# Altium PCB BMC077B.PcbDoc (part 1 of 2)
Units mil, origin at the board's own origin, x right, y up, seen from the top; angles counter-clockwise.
Board outline 3180 x 2450 mil, 4 copper layers (Top Layer, Signal Layer 1, Signal Layer 2, Bottom Layer), stack 61.2 mil thick; 102 components, 30 nets, 186 pads, 124 vias.
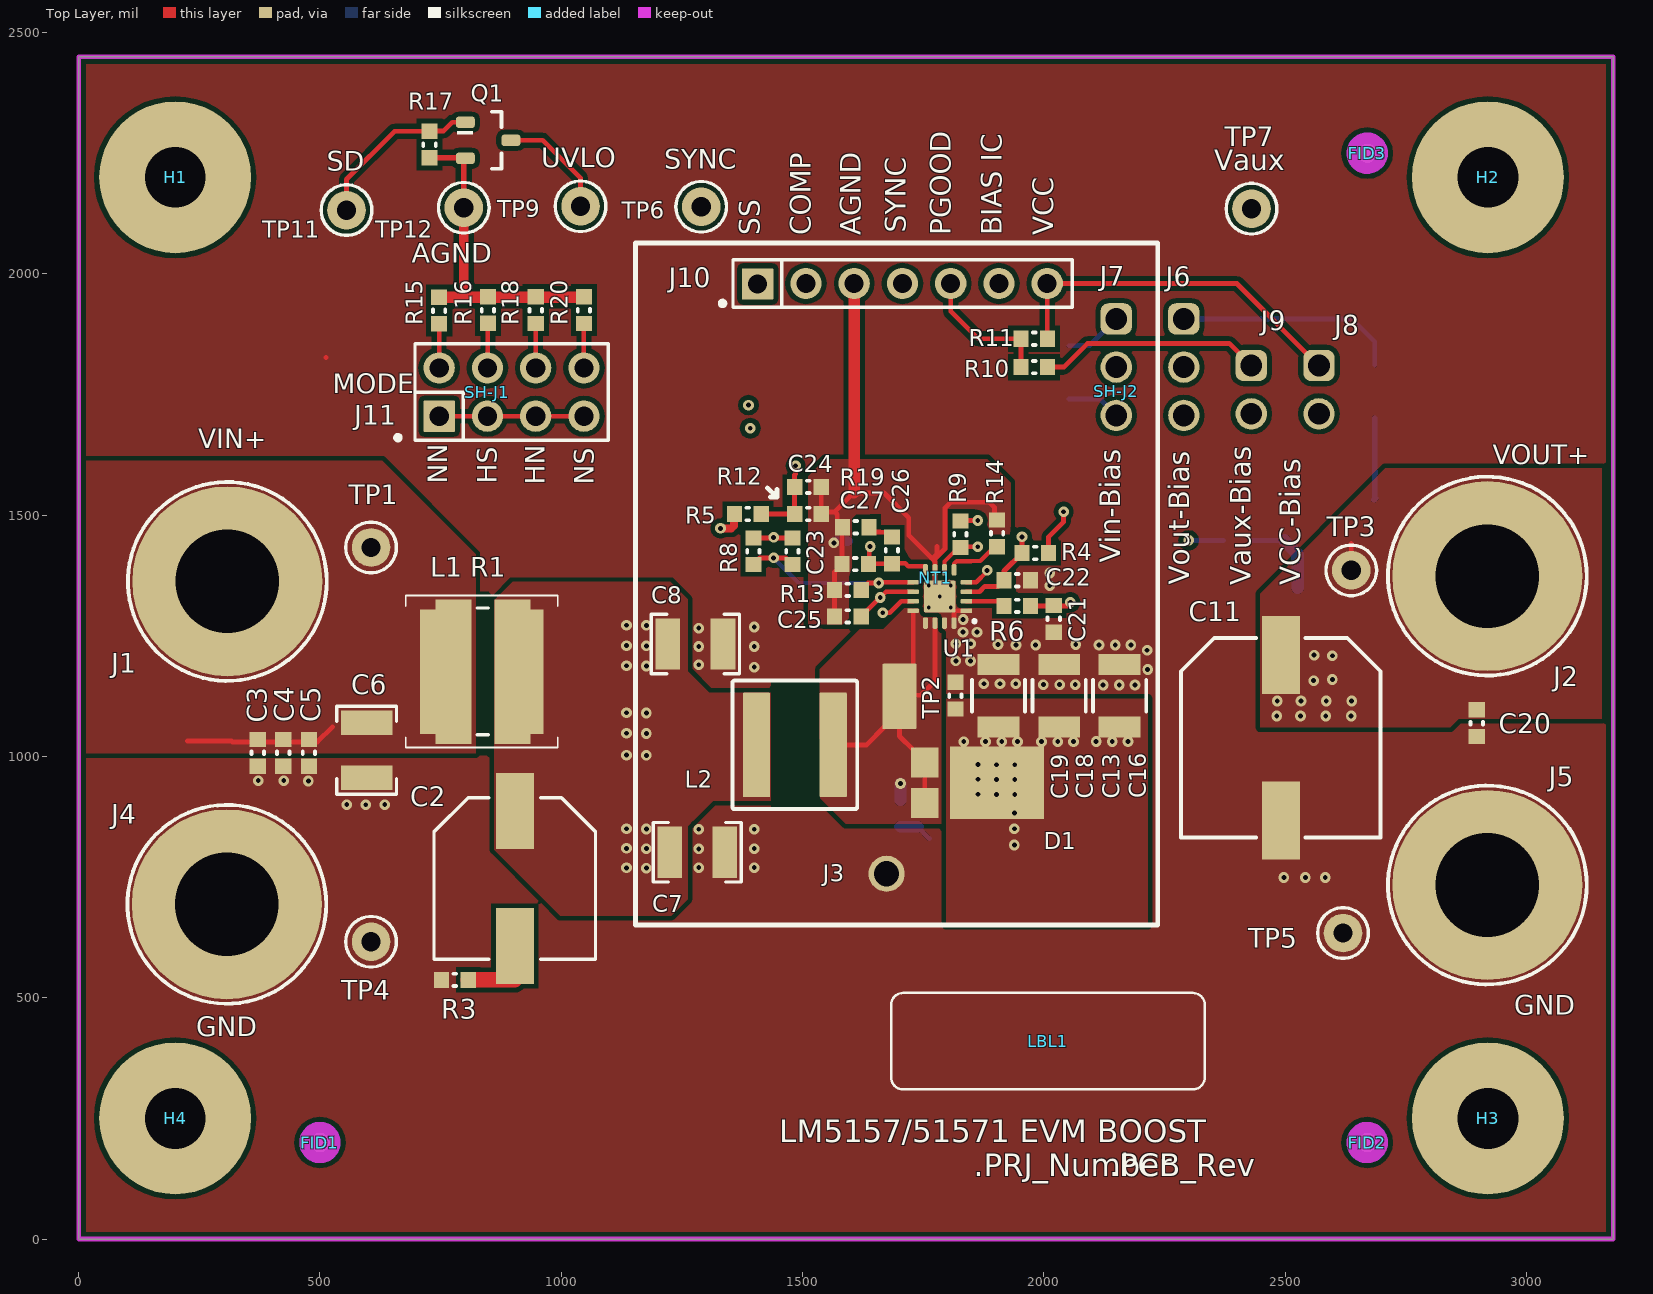
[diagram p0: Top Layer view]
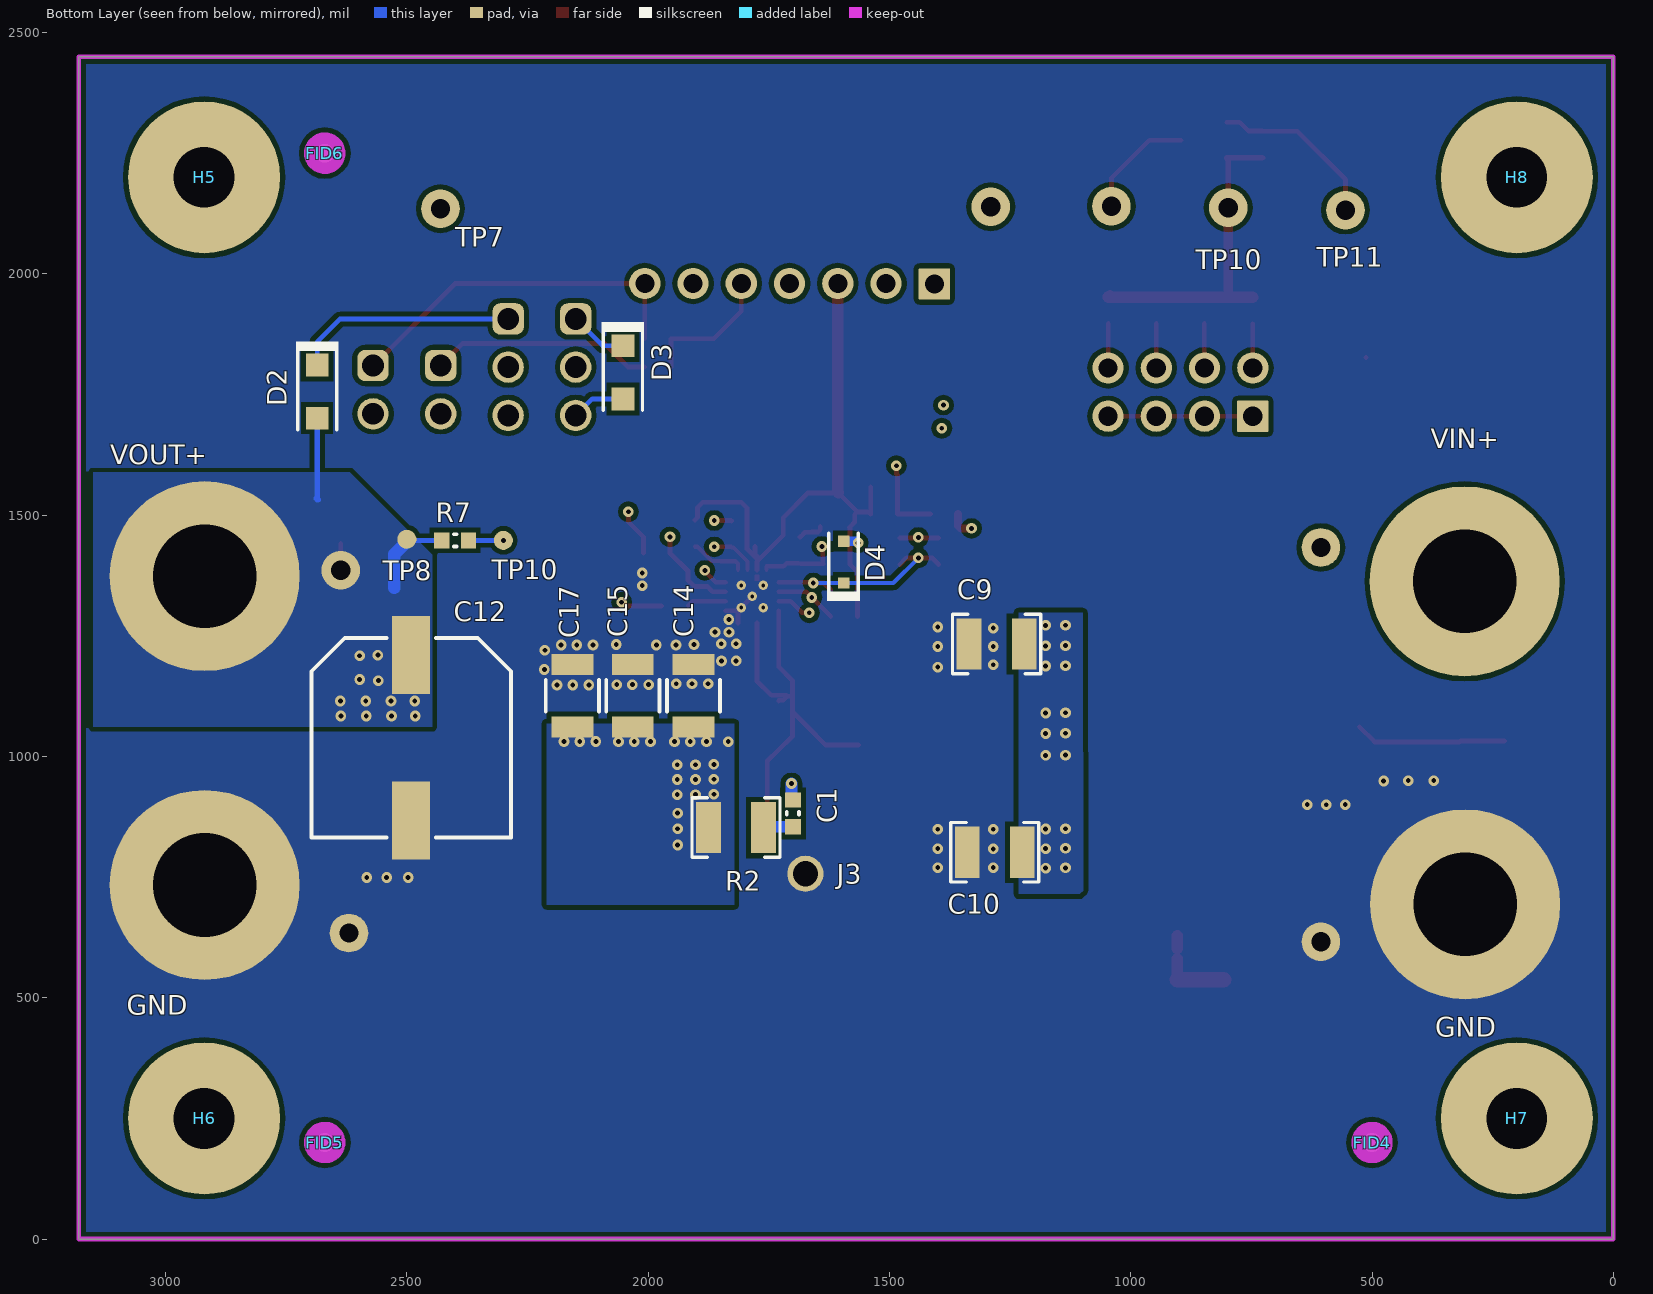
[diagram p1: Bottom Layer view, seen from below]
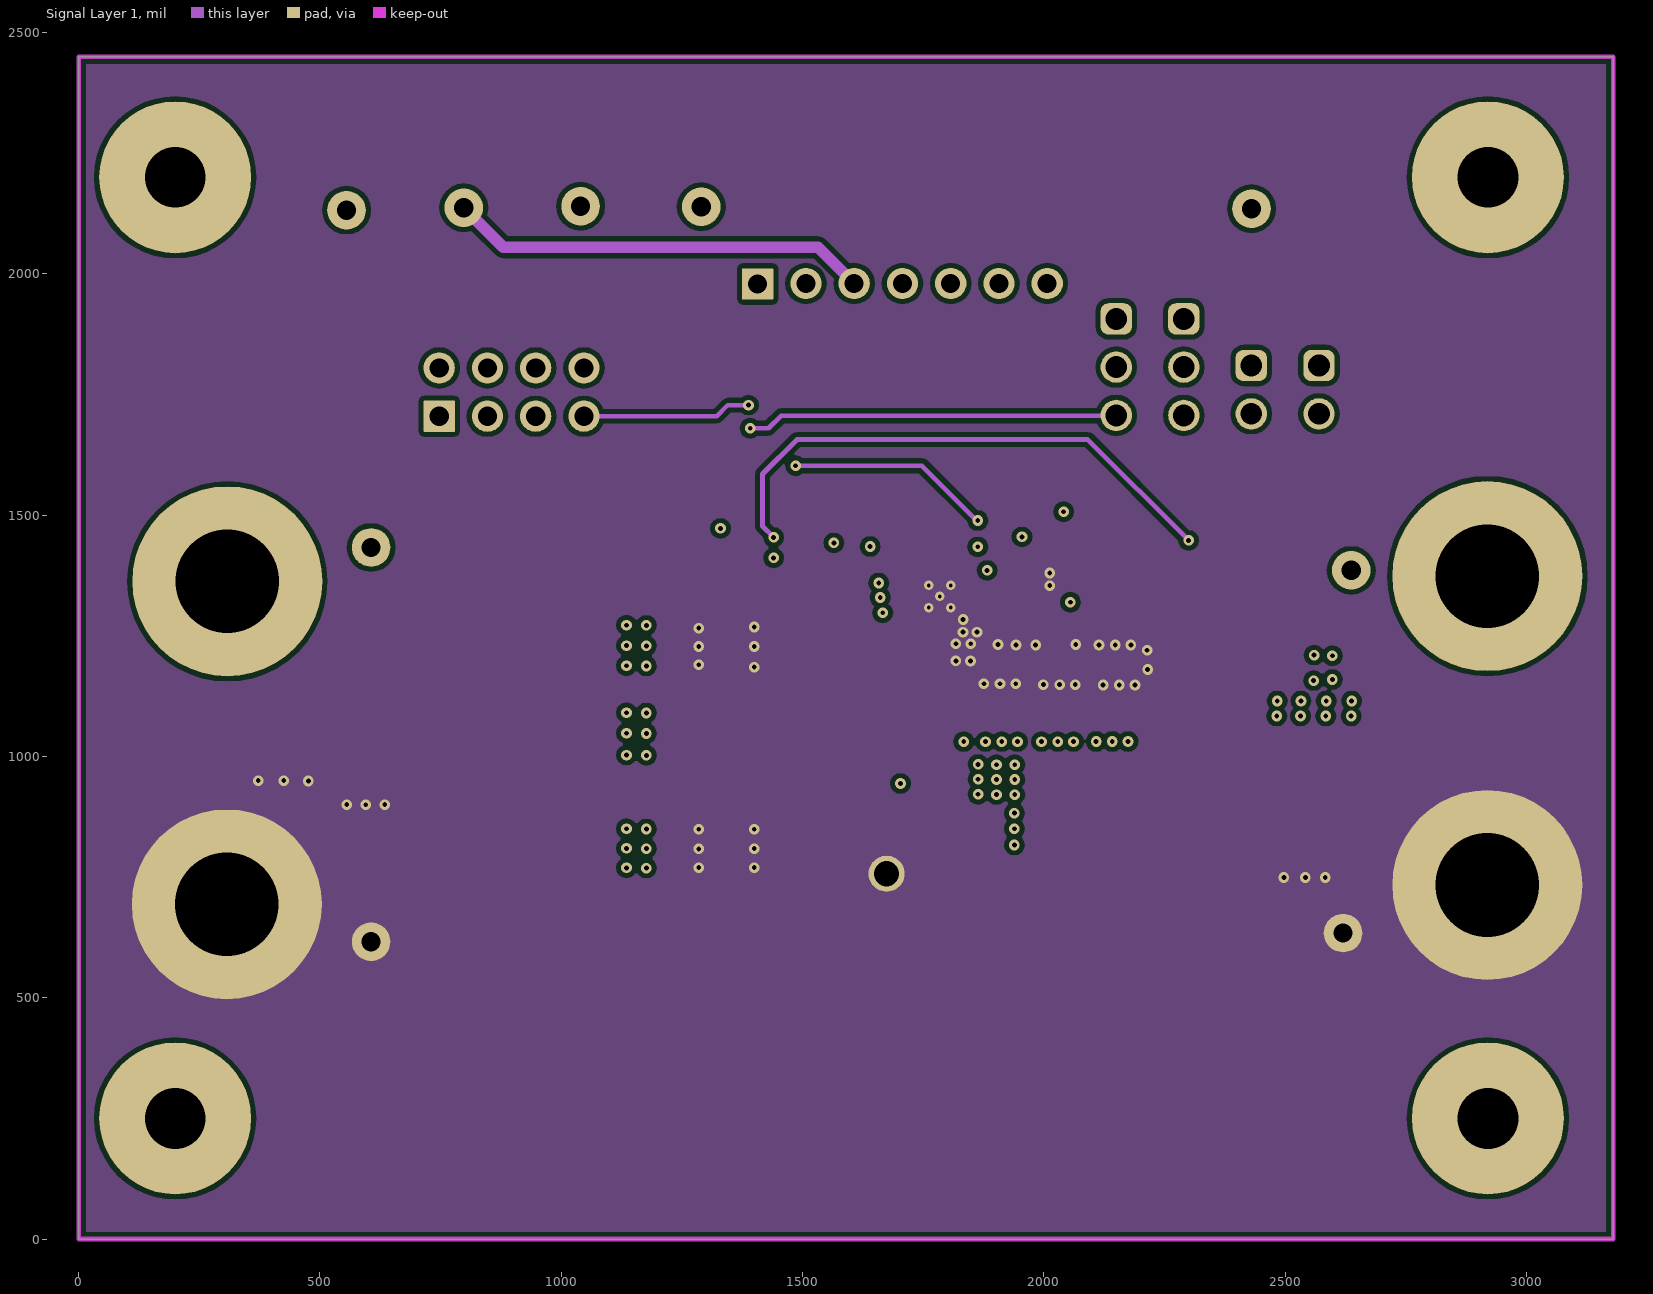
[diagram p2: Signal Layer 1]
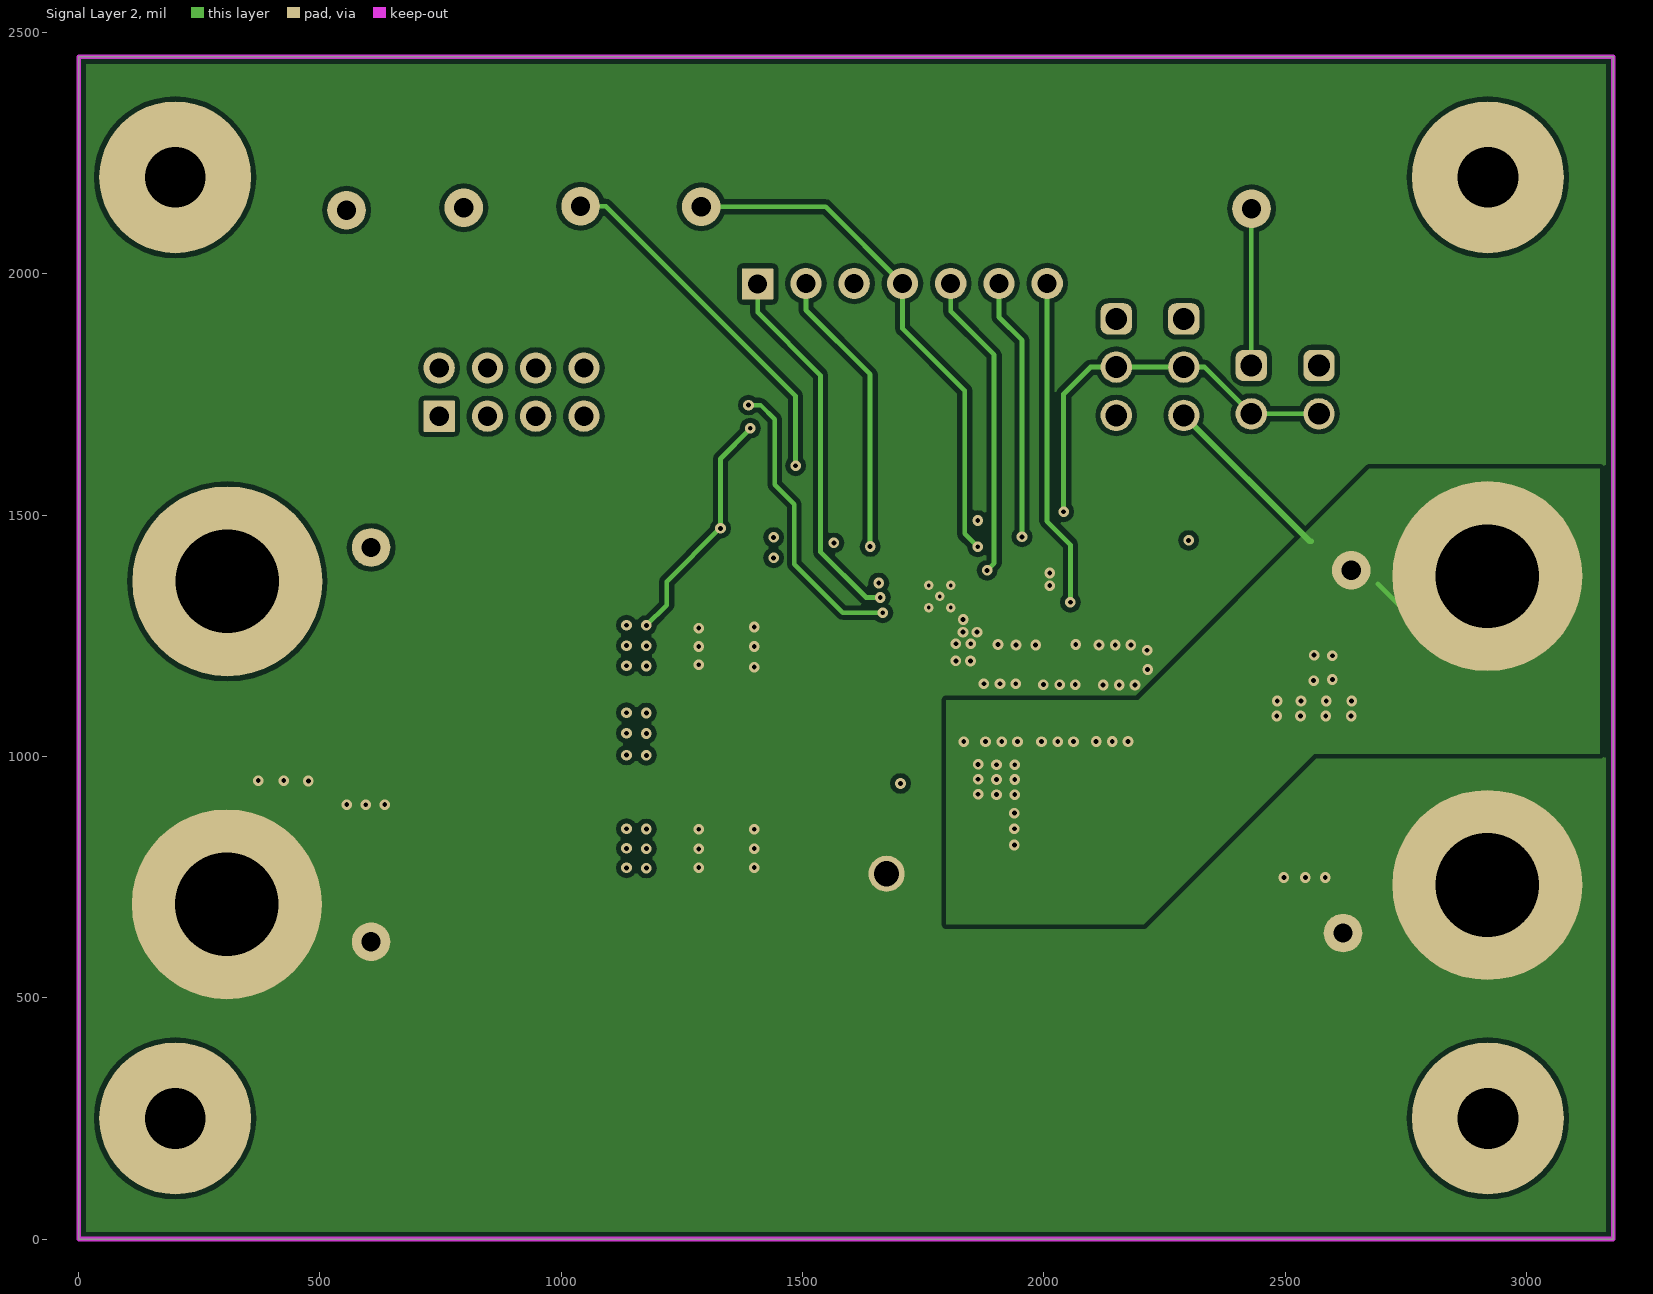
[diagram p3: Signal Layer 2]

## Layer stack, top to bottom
Top Solder: solder mask 0.4, Solder Resist, Dk 3.5
Top Layer: signal copper 2.8
Dielectric1: core 6, FR-4 High Tg, Dk 4.8
Signal Layer 1: signal copper 2.8
Dielectric 2: prepreg 38, FR-4 High Tg, Dk 4.2
Signal Layer 2: signal copper 2.8
Dielectric 3: core 6, FR-4 High Tg, Dk 4.2
Bottom Layer: signal copper 2.8
Bottom Solder: solder mask 0.4, Solder Resist, Dk 3.5

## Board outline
0,0 3180,0 3180,2450 0,2450

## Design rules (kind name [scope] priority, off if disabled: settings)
AcuteAngle [All] p1: minimum=4.50000000000000E+0001 checktracksonly=FALSE
AssemblyTestPointUsage [All] p1: valid=2
BoardOutlineClearance BoardOutlineClearance_MountingHoles [OnCopper and InComponentClass('Mounting Holes')] p1: gap=39.37 ignorepadtopadclearanceinfootprint=FALSE
BoardOutlineClearance BoardOutlineClearance_Poly [OnCopper and IsPoly] p2: gap=25 ignorepadtopadclearanceinfootprint=FALSE
BoardOutlineClearance [OnCopper and Not InComponentClass('Logo') and not InComponentClass('FiducialMark') and not InRegion(1000,500,4000,800) and not InPoly] p3: gap=50 ignorepadtopadclearanceinfootprint=FALSE
Clearance Clearance_Keepouts [((IsTrack Or IsArc) And Not InPoly) And IsFree and IsKeepOut vs ((IsTrack Or IsArc) And Not InPoly) And IsFree and IsKeepOut] p1: gap=40 ignorepadtopadclearanceinfootprint=FALSE
Clearance Clearance_Poly [InPolygon] p2: gap=10 ignorepadtopadclearanceinfootprint=TRUE
Clearance Clearance_FiducialMark [IsKeepOut and InComponentClass('FiducialMark') vs IsPad and InComponentClass('FiducialMark')] p3: gap=0 ignorepadtopadclearanceinfootprint=FALSE
Clearance [All] p4: gap=7.87 ignorepadtopadclearanceinfootprint=TRUE
ComponentClearance ComponentClearance_Shunts [InComponent('SH-J1') or InComponent('SH-J2')] p1: gap=0 collisioncheckmode=3 verticalgap=0 showdistances=FALSE
ComponentClearance ComponentClearance_L1 [HasFootprint('2512_WIDE_VISHAY') vs HasFootprint('XAL7030')] p2: gap=0 collisioncheckmode=3 verticalgap=0 showdistances=FALSE
ComponentClearance ComponentClearance_NetTie [HasFootprint('Net-Tie_10mil')] p3: gap=0 collisioncheckmode=3 verticalgap=0 showdistances=FALSE
ComponentClearance ComponentClearance_MountingHoles_FiducialMarks [InComponentClass('Mounting Holes') vs InComponentClass('FiducialMark')] p4: gap=50 collisioncheckmode=3 verticalgap=10 showdistances=FALSE
ComponentClearance ComponentClearance_Shunt [InComponentClass('Header') vs InComponentClass('Shunt')] p5: gap=0 collisioncheckmode=3 verticalgap=0 showdistances=FALSE
ComponentClearance ComponentClearance_Logo [InComponentClass('Logo')] p6: gap=50 collisioncheckmode=3 verticalgap=10 showdistances=FALSE
ComponentClearance ComponentClearance_ScrewToNut [(HasFootprint('NY PMS 440 0025 PH')) vs (HasFootprint('Keystone_1902C'))] p7: gap=5 collisioncheckmode=3 verticalgap=10 showdistances=FALSE
ComponentClearance ComponentClearance_MountingHoles [InComponentClass('Mounting Holes')] p8: gap=150 collisioncheckmode=3 verticalgap=150 showdistances=FALSE
ComponentClearance ComponentClearance_SmallPassives [HasFootprint('0201*') or HasFootprint('0402*') or HasFootprint('0508') or HasFootprint('0603*') or HasFootprint('0612') or HasFootprint('0805*') or HasFootprint('0815*') or HasFootprint('0830*') or HasFootprint('1206*') or HasFootprint('1210*') or HasFootprint('1808*') or HasFootprint('1812*') or HasFootprint('1825*') or HasFootprint('2010*') or HasFootprint('2220*') or HasFootprint('2225*') or HasFootprint('2512*') or HasFootprint('2728*') or HasFootprint('3518*') vs HasFootprint('0201*') or HasFootprint('0402*') or HasFootprint('0508') or HasFootprint('0603*') or HasFootprint('0612') or HasFootprint('0805*') or HasFootprint('0815*') or HasFootprint('0830*') or HasFootprint('1206*') or HasFootprint('1210*') or HasFootprint('1808*') or HasFootprint('1812*') or HasFootprint('1825*') or HasFootprint('2010*') or HasFootprint('2220*') or HasFootprint('2225*') or HasFootprint('2512*') or HasFootprint('2728*') or HasFootprint('3518*')] p9: gap=14.96 collisioncheckmode=3 verticalgap=10 showdistances=FALSE
ComponentClearance ComponentClearance_THtoSMT [IsThruComponent vs IsSMTComponent] p10: gap=30 collisioncheckmode=3 verticalgap=30 showdistances=FALSE
ComponentClearance ComponentClearance_THtoTH [IsThruComponent vs IsThruComponent] p11: gap=30 collisioncheckmode=3 verticalgap=30 showdistances=FALSE
ComponentClearance [All] p12: gap=20 collisioncheckmode=3 verticalgap=10 showdistances=FALSE
DiffPairsRouting [All] p1: maxlimit=100 minlimit=10 mostfreqgap=10 toplayer_minwidth=15 toplayer_maxwidth=15 toplayer_prefwidth=15 midlayer1_minwidth=15 midlayer1_maxwidth=15 midlayer1_prefwidth=15 midlayer2_minwidth=15 midlayer2_maxwidth=15 midlayer2_prefwidth=15 bottomlayer_minwidth=15 bottomlayer_maxwidth=15 bottomlayer_prefwidth=15 maxuncoupledlength=1000
FabricationTestPointUsage TestPointUsage [All] p1: valid=2 allowmultiple=FALSE
FabricationTestpoint Testpoint [All] p1: side=3 testpointundercomponent=TRUE minsize=40 maxsize=100 preferedsize=60 minholesize=0 maxholesize=40 preferedholesize=32 testpointgrid=1 allowsidetop=TRUE allowsidebottom=TRUE usegrid=TRUE gridtolerance=0.01
FanoutControl Fanout_LCC [IsLCC] p1: bgadir=Out bgaviamode=Centered fanoutstyle=Auto fanoutdirection=Alternating viagrid=1 // Fanout_LCC (Default Rule)
FanoutControl Fanout_BGA [IsBGA] p2: bgadir=Out bgaviamode=Centered fanoutstyle=Auto fanoutdirection=Alternating viagrid=1 // Fanout_BGA (Default Rule)
FanoutControl Fanout_Default [All] p4: bgadir=Out bgaviamode=Centered fanoutstyle=Auto fanoutdirection=Alternating viagrid=1 // Fanout_Default (Default Rule)
FanoutControl Fanout_Small [(CompPinCount < 5)] p5: bgadir=Out bgaviamode=Centered fanoutstyle=Auto fanoutdirection=OutThenIn viagrid=1 // Fanout_Small (Default Rule)
HoleSize [All] p1: absolutevalues=TRUE maxlimit=251 minlimit=7.87 maxpercent=80.000 minpercent=20.000
MinimumAnnularRing MinimumAnnularRing_ThermalPadVias [IsVia and InAnyComponent] p1: minimumring=5.91
MinimumAnnularRing [All] p2: minimumring=5.91
MinimumSolderMaskSliver MinimumSolderMaskSliver_Logo [InComponentClass('Logo') vs InComponentClass('Logo')] p1: minsoldermaskwidth=0.7
MinimumSolderMaskSliver [All] p2: minsoldermaskwidth=3.94
PlaneConnect [All] p1: planeconnectstyle=Relief reliefexpansion=10 reliefentries=4 reliefconductorwidth=10 reliefairgap=10
PolygonConnect [All] p1: connectstyle=Direct reliefconductorwidth=10 reliefentries=4 polygonreliefangle="90 Angle" airgapwidth=10
RoutingVias ThermalPadVias [IsVia and InAnyComponent] p1: holewidth=7.87 width=19.68 viastyle="Through Hole" minholewidth=7.87 minwidth=19.68 maxholewidth=12.99 maxwidth=23.62
RoutingVias [All] p2: holewidth=10 width=20 viastyle="Through Hole" minholewidth=7.87 minwidth=19 maxholewidth=40 maxwidth=65
SilkToBoardRegionClearance [Not ((IsComment or IsDesignator) And (Hide <> 'False')) and not InRegion(1000,500,4000,800)] p1:
SilkToSilkClearance SilkToSilkClearance_Pb-FreeLogo [(HasFootprint('Pb-Free_Overlay_Medium') OR HasFootprint('Pb-Free_Overlay_Small')) vs (HasFootprint('Pb-Free_Overlay_Medium') OR HasFootprint('Pb-Free_Overlay_Small'))] p1: silktosilkclearance=0
SilkToSilkClearance [All] p2: silktosilkclearance=3.94
SilkToSolderMaskClearance SilkToComponentPadClearance [IsPad] p1: minsilkscreentomaskgap=4 clearancetoexposedcopper=TRUE
SilkToSolderMaskClearance "Silk to Solder Mask Opening" [All] p2: minsilkscreentomaskgap=3.94 clearancetoexposedcopper=FALSE
SolderMaskExpansion [All] p1: expansion=1.97 istentingtop=FALSE
UnRoutedNet [All] p1: checkbadconnections=TRUE
Width [All] p1: maxlimit=100 minlimit=6 preferedwidth=10 checkconnectedcopper=TRUE
14 further rules are at their usual default settings.

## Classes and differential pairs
component class Label: LBL1
component class Header: J6 J7 J8 J9 J10 J11
component class BMC077B: C1 C2 C3 C4 C5 C6 C7 C8 C9 C10 C11 C12 C13 C14 C15 C16 C17 C18 C19 C20 C21 C22 C23 C24 C25 C26 C27 D1 D2 D3 D4 J1 J2 J3 J4 J5 J6 J7 J8 J9 J10 J11 L1 L2 NT1 Q1 R1 R2 R3 R4 R5 R6 R7 R8 R9 R10 R11 R12 R13 R14 R15 R16 R17 R18 R19 R20 TP1 TP2 TP3 TP4 TP5 TP6 TP7 TP8 TP9 TP10 TP11 TP12 U1
component class "Mounting Holes": H1 H2 H3 H4
component class BMC077B-HW: FID1 FID2 FID3 FID4 FID5 FID6 H1 H2 H3 H4 H5 H6 H7 H8 LBL1 SH-J1 SH-J2 ZZ1 ZZ2 ZZ3 ZZ4 ZZ5 ZZ6
component class FiducialMark: FID1 FID2 FID3 FID4 FID5 FID6
component class AssemblyNote: ZZ1 ZZ2 ZZ3 ZZ4 ZZ5 ZZ6

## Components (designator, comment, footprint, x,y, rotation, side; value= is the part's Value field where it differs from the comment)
C1 "GRM188R72A222KA01D" 0603L 1700,882 r90 bottom value=2200pF
C2 "EEE-FK2A220P" SM_RADIAL_F 903.64,747 r270 top value=22uF
C3 "C0603X102K5RACTU" 0603L 371,1007.25 r270 top value=1000pF
C4 "C0603C104K5RACAUTO" 0603L 424,1007.25 r270 top value=0.1uF
C5 "C0603X103K5RACTU" 0603L 477,1007.25 r270 top value=0.01uF
C6 "GRM32ER71H106KA12L" 1210_270 596.76,1013 r270 top value=10uF
C7 "GRM32ER71H106KA12L" 1210_270 1281.62,801.44 r0 top value=10uF
C8 "GRM32ER71H106KA12L" 1210_270 1278,1232.98 r0 top value=10uF
C9 "GRM32ER71H106KA12L" 1210_270 1278,1232.98 r0 bottom value=10uF
C10 "GRM32ER71H106KA12L" 1210_270 1281.62,801.44 r0 bottom value=10uF
C11 "EEH-ZC1H101P" Panasonic_G 2491,1038.63 r270 top value=100uF
C12 "EEH-ZC1H101P" Panasonic_G 2491,1038.63 r270 bottom value=100uF
C13 "CGA6P3X7R1H475K250AB" 1210_280 2031.7,1125.83 r90 top value=4.7uF
C14 "CGA6P3X7R1H475K250AB" 1210_280 1906.03,1125.83 r90 bottom value=4.7uF
C15 "CGA6P3X7R1H475K250AB" 1210_280 2031.7,1125.83 r90 bottom value=4.7uF
C16 "CGA6P3X7R1H475K250AB" 1210_280 2157,1125.83 r90 top value=4.7uF
C17 "CGA6P3X7R1H475K250AB" 1210_280 2157,1125.83 r90 bottom value=4.7uF
C18 "CGA6P3X7R1H475K250AB" 1210_280 1906.03,1125.83 r90 top value=4.7uF
C19 "C0603C104K5RACAUTO" 0603L 1816.84,1126 r90 top value=0.1uF
C20 "C0603C104K5RACAUTO" 0603L 2897,1069 r270 top value=0.1uF
C21 "CGA3E1X7R1C105K080AC" 0603L 2020.33,1285 r90 top value=1uF
C22 "GCJ188R72A104KA01D" 0603L 1945,1365 r0 top value=0.1uF
C23 "CGA3E2X7R1H683K080AA" 0603L 1478.8,1425 r270 top value=0.068uF
C24 "C0603C101F5GACTU" 0603L 1511.31,1558.44 r0 top value=100pF
C25 "C0603X223K5RACTU" 0603L 1593.98,1290.09 r180 top value=0.022uF
C26 "C0603C123K5RACTU" 0603L 1685,1427.03 r90 top value=0.012uF
C27 "06035A201FAT2A" 0603L 1609,1398.61 r180 top value=200pF
D1 "PMEG045V100EPDAZ" SOT1289 1862.55,945.52 r90 top value=45V
D2 "PMEG6010CEH,115" SOD-123F 2685.71,1756 r270 bottom value=60V
D3 "PMEG6010CEH,115" SOD-123F 2052.24,1795.85 r270 bottom value=60V
D4 "MMSZ5225BS-7-F" SOD-323 1595,1402.75 r90 bottom value=3V
FID1 "Fiducial" Fiducial10-20 500,200 r0 top
FID2 "Fiducial" Fiducial10-20 2670,200 r0 top
FID3 "Fiducial" Fiducial10-20 2670,2250 r0 top
FID4 "Fiducial" Fiducial10-20 500,200 r180 bottom
FID5 "Fiducial" Fiducial10-20 2670,200 r180 bottom
FID6 "Fiducial" Fiducial10-20 2670,2250 r180 bottom
H1 "NY PMS 440 0025 PH" "NY PMS 440 0025 PH" 200,2200 r0 top
H2 "NY PMS 440 0025 PH" "NY PMS 440 0025 PH" 2920,2200 r0 top
H3 "NY PMS 440 0025 PH" "NY PMS 440 0025 PH" 2920,250 r0 top
H4 "NY PMS 440 0025 PH" "NY PMS 440 0025 PH" 200,250 r0 top
H5 "1902C" Keystone_1902C 2920,2200 r180 bottom
H6 "1902C" Keystone_1902C 2920,250 r180 bottom
H7 "1902C" Keystone_1902C 200,250 r180 bottom
H8 "1902C" Keystone_1902C 200.36,2200 r180 bottom
J1 "575-8" Keystone575-8 308,1362.63 r90 top
J2 "575-8" Keystone575-8 2919,1373.63 r90 top
J3 "1040" CONN_1040 1674.19,757 r0 top
J4 "575-8" Keystone575-8 307,693.63 r90 top
J5 "575-8" Keystone575-8 2919,733.63 r90 top
J6 "61300311121" WURTH_61300311121 2290,1806.67 r270 top
J7 "61300311121" WURTH_61300311121 2150,1806.67 r270 top
J8 "61300211121" WURTH_61300211121 2570,1760 r270 top
J9 "61300211121" WURTH_61300211121 2429.74,1760 r270 top
J10 "TSW-107-07-G-S" TSW-107-XX-XXX-S 1706.98,1980 r0 top
J11 "TSW-104-07-G-D" TSW-104-07-G-D 897,1755 r0 top
L1 "XAL7030-102MEB" XAL7030 835.24,1175.83 r0 top value=1uH
L2 "XEL6030-222MEB" XEL6030_310 1484,1024 r0 top value=2.2uH
LBL1 "THT-14-423-10" Label_650x200 2008.42,410 r180 top
NT1 "Net-Tie" Net-Tie_10mil 1774.44,1370 r90 top net-tie
Q1 "BSS123" SOT-23 848.43,2276.72 r0 top value=100V
R1 "RCL12250000Z0EG" 2512_WIDE_VISHAY 837.61,1175.83 r0 top value=0
R2 "ERJ-14BQF2R0U" 1210 1818,852.63 r0 bottom value=2.00
R3 "RC0603JR-070RL" 0603L 779.69,537 r0 top value=0
R4 "RC0603JR-070RL" 0603L 1982.33,1421.56 r180 top value=0
R5 "RC0603FR-0761K9L" 0603L 1386.7,1502.4 r180 top value=61.9k
R6 "RC0603FR-074R99L" 0603L 1945,1312.05 r180 top value=4.99
R7 "RC0603FR-0710RL" 0603L 2400,1447.68 r0 bottom value=10.0
R8 "RC0603FR-0749K9L" 0603L 1398,1425.22 r90 top value=49.9k
R9 "RC0603JR-070RL" 0603L 1827,1460.44 r270 top value=0
R10 "RC0603FR-07100KL" 0603L 1980,1806.67 r0 top value=100k
R11 "RC0603FR-07100KL" 0603L 1980,1865.5 r0 top value=100k
R12 "RC0603FR-0771K5L" 0603L 1511.31,1502.4 r180 top value=71.5k
R13 "RC0603FR-074K53L" 0603L 1593.98,1345.2 r0 top value=4.53k
R14 "RC0603FR-079K53L" 0603L 1903,1462.25 r270 top value=9.53k
R15 "RC0603JR-070RL" 0603L 747,1924 r90 top value=0
R16 "RC0603FR-0737K4L" 0603L 848,1925 r270 top value=37.4k
R17 "RC0603FR-0710KL" 0603L 727,2268 r90 top value=10.0k
R18 "RC0603FR-0762KL" 0603L 947,1924.81 r270 top value=62.0k
R19 "RC0603FR-072K49L" 0603L 1610,1475 r0 top value=2.49k
R20 "RC0603FR-07100KL" 0603L 1047,1924.81 r270 top value=100k
SH-J1 "M7582-05" Harwin_M7582-05 847,1755 r90 top
SH-J2 "M7582-05" Harwin_M7582-05 2150,1756.67 r90 top
TP1 "VIN+" Keystone5000 605.93,1433 r90 top
TP2 "SW" Keystone_5017 1700.88,1124.63 r270 top
TP3 "VOUT+" Keystone5000 2637,1385.61 r90 top
TP4 "VIN-" Keystone5001 605.93,616 r90 top
TP5 "GND" Keystone5001 2619.92,634 r90 top
TP6 "SYNC" Keystone5004 1290,2139 r0 top
TP7 "VAUX" Keystone5000 2430.34,2135 r90 top
TP8 "VOUT+" TP_SM_1MM 2500,1450 r90 bottom
TP9 "UVLO" Keystone5002 1040,2140 r0 top
TP10 "VOUT-" TP_SM_1MM 2300,1447.68 r90 bottom
TP11 "SD" Keystone5002 555,2132 r0 top
TP12 "AGND" Keystone5001 798,2137 r180 top
U1 "LM5157QRTERQ1" RTE0016K 1784.32,1331.42 r180 top
ZZ1 "This Assembly Note is for PCB labels only" AssemblyNoteLabel 0,3050 r0 top
ZZ2 "These assemblies are ESD sensitive, ESD precautions shall be observed." AssemblyNote 0,2950 r0 top
ZZ3 "These assemblies must be clean and free from flux and all contaminants. Use of no clean flux is not acceptable." AssemblyNote 0,2850 r0 top
ZZ4 "These assemblies must comply with workmanship standards IPC-A-610 Class 2, unless otherwise specified." AssemblyNote 0,2750 r0 top
ZZ5 "Install Shunt Jumper SH-J1 onto J11 pins 3 - 4 (HS)." AssemblyNote 0,2650 r0 top
ZZ6 "Install Shunt Jumper SH-J2 onto J7 pins 2 - 3 (Vin-Bias)." AssemblyNote 0,2550 r0 top

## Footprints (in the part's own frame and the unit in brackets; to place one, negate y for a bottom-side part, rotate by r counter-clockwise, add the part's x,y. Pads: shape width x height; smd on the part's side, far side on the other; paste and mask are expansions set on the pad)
0603L [mm] "0603 from SM-752 data"
  rect 0.8x0.85 smd: 1(-0.7,0) 2(0.7,0)
  silkscreen extent -0.07,-0.33 0.07,0.33, body extent -0.87,-0.47 0.87,0.47, height 1
1210 [mm] "1210 from SM-752 data"
  rect 1.3x2.7 smd: 1(-1.45,0) 2(1.45,0)
  silkscreen extent -2.32,-1.57 2.32,1.57, body extent -1.7,-1.35 1.7,1.35, height 1.35
1210_270 [mm] "1210"
  rect 1.3x2.7 smd: 1(-1.45,0) 2(1.45,0)
  silkscreen extent -2.32,-1.57 2.32,1.57, body extent -1.7,-1.35 1.7,1.35, height 2.7
1210_280 [mm] "SMD, 2-Leads, Body 3.6x2.8mm, Height 2.8mm"
  rect 1.1x2.2 smd: 1(-1.65,0) 2(1.65,0)
  silkscreen extent -0.84,-1.4 0.84,1.4, body extent -1.8,-1.4 1.8,1.4, height 2.8
2512_WIDE_VISHAY [mm] "Vishay recommended land pattern"
  rect 1.9x7.6 smd: 1(-1.55,0) 2(1.55,0)
  silkscreen extent -0.3,-3.32 0.3,3.35, body extent -1.7,-3.25 1.7,3.25, height 0.9
AssemblyNote [mil] "Assembly Note"
AssemblyNoteLabel [mil] "Assembly Note for PCB Labels"
CONN_1040 [mil] "Test Point, PC  test point Terminal"
  round 75 hole 52: 1(0,0)
  body extent -55,-12 55,13, height 276
Fiducial10-20 [mm]
  round 1 smd mask+0.5: 1(0,0)
  Top Layer keep-out circle w1.178: c0,0 r0.5
Harwin_M7582-05 [mil] "Single Operation 2.54mm Pitch Open Top Jumper Socket"
  body extent -98,-47 98,47, height 236
Keystone575-8 [mm] "Banana Jack"
  round 10 hole 5.45: 1(0,0)
  silkscreen extent -5.23,-5.23 5.23,5.23, body extent -3.92,-3.94 3.95,3.94, height 2.36
Keystone5000 [mil] "For Keystone 500x miniature loop terminals"
  round 80 hole 40: 1(0,0)
  silkscreen extent -52,-52 52,52, body extent -49,-49 49,49, height 182
Keystone5001 [mil] "For Keystone 500x miniature loop terminals"
  round 80 hole 40: 1(0,0)
  silkscreen extent -52,-52 52,52, body extent -49,-49 49,49, height 182
Keystone5002 [mil] "For Keystone 500x miniature loop terminals"
  round 80 hole 40: 1(0,0)
  silkscreen extent -52,-52 52,52, body extent -49,-49 49,49, height 182
Keystone5004 [mil] "For Keystone 500x miniature loop terminals"
  round 80 hole 40: 1(0,0)
  silkscreen extent -52,-52 52,52, body extent -49,-49 49,49, height 182
Keystone_1902C [mil] "Hex Standoff, 4-40 threaded, nylon"
  round 1 on Mech4: 0(0,0)
  body extent -145,-126 146,126, height 501
Keystone_5017 [mm] "PC Test Point, SMT"
  rrect6% 3.43x1.78 smd: 1(0,0)
  body extent -1.35,-0.51 1.35,0.51, height 1.51
Label_650x200 [mil] "Thermal Transfer Label"
  round 1 on Mech13: 0(0,0)
  silkscreen extent -325,-100 325,100, body extent -325,-100 325,100, height 1
Net-Tie_10mil [mil] "10mil net tie, no solder mask opening, no solder paste"
  rect 10x10 smd paste-5 mask-5: 1(-10,0) 2(10,0)
  Top Layer region: -6,5 6,5 6,-5 -6,-5
"NY PMS 440 0025 PH" [mm] "4-40 nylon screw and mounting hole"
  round 8 hole 3.2: 1(0,0)
  body extent -3.3,-3.3 3.3,3.3, height 2.69
Panasonic_G [mm] "SMD, 2-Leads, Dia 10mm"
  rect 4.1x2 smd: 1(-4.35,0) 2(4.35,0)
  silkscreen extent -5.25,-5.25 5.25,5.25, body extent -5.25,-5.25 5.25,5.25, height 10.51
RTE0016K [mm] "WQFN-16"
  rrect42% 0.6x0.24 smd paste+0: 1(-1.4,0.75) 2(-1.4,0.25) 3(-1.4,-0.25) 4(-1.4,-0.75) 9(1.4,-0.75) 10(1.4,-0.25) 11(1.4,0.25) 12(1.4,0.75)
  rrect42% 0.24x0.6 smd paste+0: 5(-0.75,-1.4) 6(-0.25,-1.4) 7(0.25,-1.4) 8(0.75,-1.4) 13(0.75,1.4) 14(0.25,1.4) 15(-0.25,1.4) 16(-0.75,1.4)
  rrect6% 1.66x1.66 smd paste-0.075: 17(0,0)
  silkscreen extent -1.86,1.26 -1.79,1.34, body extent -1.5,-1.5 1.5,1.5, height 0.8
SM_RADIAL_F [mm] "8 x 10.2mm:  Panasonic F"
  rect 4x2 smd: 1(-3.55,0) 2(3.55,0)
  silkscreen extent -4.25,-4.25 4.25,4.25, body extent -4.25,-4.25 4.25,4.25, height 10.5
SOD-123F [mm] "NXP recommended land pattern"
  rect 1.2x1.2 smd paste-0.05: 1(-1.4,0) 2(1.4,0)
  silkscreen extent -2.64,-1.12 2.01,1.12, body extent -1.8,-0.85 1.8,0.85, height 1.2
SOD-323 [mm] "NXP recommended land pattern"
  rect 0.6x0.6 smd paste-0.05: 1(-1.1,0) 2(1.1,0)
  silkscreen extent -2.06,-0.86 1.53,0.86, body extent -1.3,-0.67 1.3,0.68, height 1.1
SOT1289 [mm] "CFP15, Nexperia recommended land pattern"
  rect 1.6x1.44 smd paste-0.8 mask+0.1: 1(-1.065,2.78) 2(1.065,2.78)
  rect 3.8x4.96 smd paste-2.48 mask+0.1: 3(0,-1.02)
  body extent -2.15,-3.25 2.15,3.25, height 0.79
SOT-23 [mm] "SOT23, 3-Leads, Body 2.9x1.3mm, Pitch 0.95mm, Lead Span 2.5mm, IPC Medium Density"
  rrect50% 1x0.6 smd: 1(-1.2,0.95) 2(-1.2,-0.95) 3(1.2,0)
  silkscreen extent -1.63,-1.5 0.7,1.5, body extent -1.16,-1.45 1.21,1.45, height 1
TP_SM_1MM [mm] "1mm Test Point, SMT"
  round 1 smd paste-0.5: 1(0,0)
TSW-104-07-G-D [mm] "Samtec 100mil, 2x4, 230 mil above insulator"
  rrect6% 1.65x1.65 hole 1.016: 1(-3.81,-1.27)
  round 1.65 hole 1.016: 2(-3.81,1.27) 3(-1.27,-1.27) 4(-1.27,1.27) 5(1.27,-1.27) 6(1.27,1.27) 7(3.81,-1.27) 8(3.81,1.27)
  silkscreen extent -6.1,-2.54 5.08,2.54, body extent -5.08,-2.54 5.08,2.54, height 8.38
TSW-107-XX-XXX-S [mm] "2.54mm pitch, 7 pin, terminal strip; straight, single row"
  rrect6% 1.65x1.65 hole 1: 1(-7.62,-0.025)
  round 1.65 hole 1: 2(-5.08,0) 3(-2.54,0) 4(0,0) 5(2.54,0) 6(5.08,0) 7(7.62,0)
  silkscreen extent -9.59,-1.25 8.93,1.25, body extent -8.89,-1.27 8.89,1.27, height 8.38
WURTH_61300211121 [mm] "Header, 2.54mm, 2x1, TH"
  rrect50% 1.65x1.65 hole 1.15: 1(-1.27,0)
  round 1.65 hole 1.15: 2(1.27,0)
  body extent -2.54,-1.27 2.54,1.27, height 8.54
WURTH_61300311121 [mm] "Header, 2.54mm, 3x1, TH"
  rrect50% 1.65x1.65 hole 1.15: 1(-2.54,0)
  round 1.65 hole 1.15: 2(0,0) 3(2.54,0)
  body extent -3.81,-1.27 3.81,1.27, height 8.54
XAL7030 [mm] "Coilcraft XAL7030 7.5 x.7.5 x 3.1 mm"
  rect 1.78x6.55 smd: 1(-2.36,0) 2(2.36,0)
  silkscreen extent -4,-4 4,4, body extent -4,-4 4,4, height 3.1
XEL6030_310 [mm] "SMD, 2-Leads, Body 66.36x6.56 mm"
  rrect7% 1.43x5.5 smd: 1(-2.02,0) 2(2.02,0)
  silkscreen extent -3.28,-3.38 3.28,3.38, body extent -3.28,-3.38 3.28,3.38, height 3.1

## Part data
C1: library part CMP-0007475-4, "CAP, CERM, 2200 pF, 100 V, +/- 10%, X7R, 0603", Cap_Case=0603, Manufacturer=MuRata, Supplier Part Number 1=490-1478-1-ND, TempCo=X7R, Tolerance_%=10%, Value1=Unknown, Value2=100V, ValueDisplayed=2200pF
C2: library part CMP-0011202-2, "CAP, AL, 22 uF, 100 V, +/- 20%, 1.3 ohm, AEC-Q200 Grade 2, SMD", Cap_Case=F, Manufacturer=Panasonic, Supplier Part Number 1=PCE3845CT-ND, Tolerance_%=20%, Value1="1.3 ohm", Value2=100V, ValueDisplayed=22uF
C3: library part CMP-0006976-5, "CAP, CERM, 1000 pF, 50 V, +/- 10%, X7R, 0603", Cap_Case=0603, Manufacturer=Kemet, Supplier Part Number 1=399-5348-1-ND, TempCo=X7R, Tolerance_%=10%, Value1=Unknown, Value2=50V, ValueDisplayed=1000pF
C4 C19 C20: library part CMP-0079602-1, "CAP, CERM, 0.1 µF, 50 V,+/- 10%, X7R, AEC-Q200 Grade 1, 0603", Cap_Case=0603, Manufacturer=Kemet, Supplier Part Number 1=399-6856-1-ND, TempCo=X7R, Tolerance_%=10%, Value2=50V, ValueDisplayed=0.1µF
C5: library part CMP-0006978-4, "CAP, CERM, 0.01 uF, 50 V, +/- 10%, X7R, 0603", Cap_Case=0603, Manufacturer=Kemet, Supplier Part Number 1=399-5346-1-ND, TempCo=X7R, Tolerance_%=10%, Value1=Unknown, Value2=50V, ValueDisplayed=0.01uF
C6 C7 C8 C9 C10: library part CMP-0009226-3, "CAP, CERM, 10 uF, 50 V, +/- 10%, X7R, 1210", Cap_Case=1210, Manufacturer=MuRata, Supplier Part Number 1=490-6544-1-ND, TempCo=X7R, Tolerance_%=10%, Value1=Unknown, Value2=50V, ValueDisplayed=10uF
C11 C12: library part CMP-0064994-2, "CAP, Polymer Hybrid, 100 uF, 50 V,+/- 20%, 0.028 ohm, AEC-Q200 Grade 1, D10xL10.2mm SMD", Cap_Case=10x10.2mm, Manufacturer=Panasonic, Supplier Part Number 1=P15462CT-ND, Tolerance_%=20%, Value1="0.028 ohm", Value2=50V, ValueDisplayed=100uF
C13 C14 C15 C16 C17 C18: library part CMP-0009162-2, "CAP, CERM, 4.7 uF, 50 V, +/- 10%, X7R, AEC-Q200 Grade 1, 1210", Cap_Case=1210_280, Manufacturer=TDK, Supplier Part Number 1=445-6999-1-ND, TempCo=X7R, Tolerance_%=10%, Value1="0.003166 ohm", Value2=50V, ValueDisplayed=4.7uF
C21: library part CMP-0079607-1, "CAP, CERM, 1 µF, 16 V,+/- 10%, X7R, AEC-Q200 Grade 1, 0603", Cap_Case=0603, Manufacturer=TDK, Supplier Part Number 1=445-12539-1-ND, TempCo=X7R, Tolerance_%=10%, Value2=16V, ValueDisplayed=1µF
C22: library part CMP-0064935-4, "CAP, CERM, 0.1 uF, 100 V,+/- 10%, X7R, AEC-Q200 Grade 1, 0603", Cap_Case=0603, Manufacturer=MuRata, Supplier Part Number 1=490-13420-1-ND, TempCo=X7R, Tolerance_%=10%, Value1=Unknown, Value2=100V, ValueDisplayed=0.1uF
C23: library part CMP-0007080-5, "CAP, CERM, 0.068 uF, 50 V, +/- 10%, X7R, AEC-Q200 Grade 1, 0603", Cap_Case=0603, Manufacturer=TDK, Supplier Part Number 1=445-5665-1-ND, TempCo=X7R, Tolerance_%=10%, Value1="0.035979 ohm", Value2=50V, ValueDisplayed=0.068uF
C24: library part CMP-0080091-1, "CAP, CERM, 100 pF, 50 V,+/- 1%, C0G/NP0, 0603", Cap_Case=0603, Manufacturer=Kemet, Supplier Part Number 1=399-7819-1-ND, TempCo=C0G/NP0, Tolerance_%=1%, Value2=50V, ValueDisplayed=100pF
C25: library part CMP-0006984-4, "CAP, CERM, 0.022 uF, 50 V, +/- 10%, X7R, 0603", Cap_Case=0603, Manufacturer=Kemet, Supplier Part Number 1=399-5340-1-ND, TempCo=X7R, Tolerance_%=10%, Value1=Unknown, Value2=50V, ValueDisplayed=0.022uF
C26: library part CMP-0084236-1, "CAP, CERM, 0.012 µF, 50 V,+/- 10%, X7R, AEC-Q200 Grade 1, 0603", Cap_Case=0603, Manufacturer=Kemet, TempCo=X7R, Tolerance_%=10%, Value2=50V, ValueDisplayed=0.012µF
C27: library part CMP-0080089-1, "CAP, CERM, 200 pF, 50 V,+/- 1%, C0G/NP0, 0603", Cap_Case=0603, Manufacturer=AVX, Supplier Part Number 1=478-6030-1-ND, TempCo=C0G/NP0, Tolerance_%=1%, Value2=50V, ValueDisplayed=200pF
D1: library part CMP-0083733-3, "Diode, Schottky, 45 V, 10 A, AEC-Q101, CFP15", Manufacturer=Nexperia, Value1=10A, Value2=0.49V
D2 D3: library part CMP-0028377-2, "Diode, Schottky, 60 V, 1 A, SOD-123F", Manufacturer=Nexperia, Value1=1A, Value2=0.57V
D4: library part CMP-0005848-3, "Diode, Zener, 3 V, 200 mW, SOD-323", Manufacturer="Diodes Inc.", Power_W=200mW, Value1=0.2W
FID1 FID2 FID3 FID4 FID5 FID6: library part CMP-0077181-1, "Fiducial mark.  There is nothing to buy or mount.", Manufacturer=N/A
H1 H2 H3 H4: library part CMP-0003617-1, "Machine Screw, Round, #4-40 x 1/4, Nylon, Philips panhead", Manufacturer="B&F Fastener Supply", Supplier Part Number 1=H542-ND
H5 H6 H7 H8: library part CMP-0003610-1, "Standoff, Hex, 0.5\"L #4-40 Nylon", Manufacturer=Keystone, Supplier Part Number 1=36-1902C-ND
J1 J2 J4 J5: library part CMP-0055166-2, "Standard Banana Jack, Uninsulated, 8.9mm", Manufacturer=Keystone, Supplier Part Number 1=36-575-8-ND
J3: library part CMP-0055161-1, "TEST POINT SLOTTED .118\", TH", Manufacturer=Keystone, Supplier Part Number 1=36-1040-ND
J6 J7: library part CMP-0054796-2, "Header, 2.54 mm, 3x1, Gold, TH", Color=Black, Manufacturer="Wurth Elektronik", Supplier Part Number 1=732-5316-ND
J8 J9: library part CMP-0054794-2, "Header, 2.54 mm, 2x1, Gold, TH", Color=Black, Manufacturer="Wurth Elektronik", Supplier Part Number 1=732-5315-ND
J10: library part CMP-0075416-1, "Header, 100mil, 7x1, Gold, TH", Color=Black, Current_A=6.3A, Manufacturer=Samtec, Supplier Part Number 1=SAM1029-07-ND, Voltage_V=550V
J11: library part CMP-0075408-3, "Header, 100mil, 4x2, Gold, TH", Color=Black, Current_A=6.3A, Manufacturer=Samtec, Supplier Part Number 1=SAM1028-04-ND, Voltage_V=550V
L1: library part CMP-0061033-1, "Inductor, Shielded, Composite, 1 uH, 21.8 A, 0.00455 ohm, SMD", Manufacturer=Coilcraft, Value1="0.00455 ohm", Value2=21.8A, ValueDisplayed=1uH
L2: library part CMP-0061100-1, "Inductor, Shielded, Composite, 2.2 uH, 10 A, 0.01397 ohm, AEC-Q200 Grade 1, SMD", Manufacturer=Coilcraft, Value1="0.01397 ohm", Value2=10A, ValueDisplayed=2.2uH
LBL1: library part CMP-0003625-1, "Thermal Transfer Printable Labels, 0.650\" W x 0.200\" H - 10,000 per roll", Manufacturer=Brady, Supplier Part Number 1=97C5133
NT1: library part CMP-0078142-4, "Single point connection between nets.", Manufacturer=N/A
Q1: library part CMP-0000947-2, "MOSFET, N-CH, 100 V, 0.17 A, SOT-23", Alternate Manufacturer=None, Manufacturer="Fairchild Semiconductor", Supplier Part Number 1=BSS123NCT-ND, Value1=1, Value2="1.8 nC"
R1: library part CMP-0015368-2, "RES, 0, 5%, 2 W, 2512 WIDE", Manufacturer="Vishay Draloric", Power_W=2W, Supplier Part Number 1=RCL0.0ECT-ND, TempCo=ppm/C, Tolerance_%=5%, Value_Code=0000, ValueDisplayed=0
R2: library part CMP-0015029-2, "RES, 2.00, 1%, 0.5 W, AEC-Q200 Grade 0, 1210", Manufacturer=Panasonic, Power_W=500mW, Supplier Part Number 1=P17258CT-ND, TempCo="100 ppm/C", Tolerance_%=1%, Value2=0.5W, Value_Code=2R00, ValueDisplayed=2.00
R3 R4 R9 R15: library part CMP-0025885-5, "RES, 0, 5%, 0.1 W, 0603", Manufacturer=Yageo, Power_W=100mW, Supplier Part Number 1=311-0.0GRCT-ND, TempCo="200 ppm/C", Tolerance_%=5%, Value2=0.1W, Value_Code=0000, ValueDisplayed=0
R5: library part CMP-0023216-5, "RES, 61.9 k, 1%, 0.1 W, 0603", Manufacturer=Yageo, Power_W=100mW, Supplier Part Number 1=311-61.9KHRCT-ND, TempCo="100 ppm/C", Tolerance_%=1%, Value2=0.1W, Value_Code=61k9, ValueDisplayed=61.9k
R6: library part CMP-0023161-5, "RES, 4.99, 1%, 0.1 W, 0603", Manufacturer=Yageo, Power_W=100mW, Supplier Part Number 1=311-4.99HRCT-ND, TempCo="200 ppm/C", Tolerance_%=1%, Value2=0.1W, Value_Code=4R99, ValueDisplayed=4.99
R7: library part CMP-0022751-4, "RES, 10.0, 1%, 0.1 W, 0603", Manufacturer=Yageo, Power_W=100mW, Supplier Part Number 1=311-10.0HRCT-ND, TempCo="100 ppm/C", Tolerance_%=1%, Value2=0.1W, Value_Code=10R0, ValueDisplayed=10.0
R8: library part CMP-0023142-5, "RES, 49.9 k, 1%, 0.1 W, 0603", Manufacturer=Yageo, Power_W=100mW, Supplier Part Number 1=311-49.9KHRCT-ND, TempCo="100 ppm/C", Tolerance_%=1%, Value2=0.1W, Value_Code=49k9, ValueDisplayed=49.9k
R10 R11 R20: library part CMP-0022735-5, "RES, 100 k, 1%, 0.1 W, 0603", Manufacturer=Yageo, Power_W=100mW, Supplier Part Number 1=311-100KHRCT-ND, TempCo="100 ppm/C", Tolerance_%=1%, Value2=0.1W, Value_Code=100k
R12: library part CMP-0023259-5, "RES, 71.5 k, 1%, 0.1 W, 0603", Manufacturer=Yageo, Power_W=100mW, Supplier Part Number 1=311-71.5KHRCT-ND, TempCo="100 ppm/C", Tolerance_%=1%, Value2=0.1W, Value_Code=71k5, ValueDisplayed=71.5k
R13: library part CMP-0023150-5, "RES, 4.53 k, 1%, 0.1 W, 0603", Manufacturer=Yageo, Power_W=100mW, Supplier Part Number 1=311-4.53KHRCT-ND, TempCo="100 ppm/C", Tolerance_%=1%, Value2=0.1W, Value_Code=4k53, ValueDisplayed=4.53k
R14: library part CMP-0023335-5, "RES, 9.53 k, 1%, 0.1 W, 0603", Manufacturer=Yageo, Power_W=100mW, Supplier Part Number 1=311-9.53KHRCT-ND, TempCo="100 ppm/C", Tolerance_%=1%, Value2=0.1W, Value_Code=9k53, ValueDisplayed=9.53k
R16: library part CMP-0023062-5, "RES, 37.4 k, 1%, 0.1 W, 0603", Manufacturer=Yageo, Power_W=100mW, Supplier Part Number 1=311-37.4KHRCT-ND, TempCo="100 ppm/C", Tolerance_%=1%, Value2=0.1W, Value_Code=37k4, ValueDisplayed=37.4k
R17: library part CMP-0022746-5, "RES, 10.0 k, 1%, 0.1 W, 0603", Manufacturer=Yageo, Power_W=100mW, Supplier Part Number 1=311-10.0KHRCT-ND, TempCo="100 ppm/C", Tolerance_%=1%, Value2=0.1W, Value_Code=10k0, ValueDisplayed=10.0k
R18: library part CMP-0023220-5, "RES, 62.0 k, 1%, 0.1 W, 0603", Manufacturer=Yageo, Power_W=100mW, Supplier Part Number 1=311-62.0KHRCT-ND, TempCo="100 ppm/C", Tolerance_%=1%, Value2=0.1W, Value_Code=62k0, ValueDisplayed=62.0k
R19: library part CMP-0022990-5, "RES, 2.49 k, 1%, 0.1 W, 0603", Manufacturer=Yageo, Power_W=100mW, Supplier Part Number 1=311-2.49KHRCT-ND, TempCo="100 ppm/C", Tolerance_%=1%, Value2=0.1W, Value_Code=2k49, ValueDisplayed=2.49k
SH-J1 SH-J2: library part CMP-0078738-1, "Single Operation 2.54mm Pitch Open Top Jumper Socket", Manufacturer=Harwin, Supplier Part Number 1=952-2881-ND
TP1 TP3 TP7: library part CMP-0055137-1, "Test Point, Miniature, Red, TH", Color=Red, Manufacturer=Keystone, PartNumber=5000, Supplier Part Number 1=36-5000-ND
TP2: library part CMP-0078225-1, "PC Test Point, SMT", Manufacturer=Keystone, PartNumber=5017, Supplier Part Number 1=36-5017CT-ND
TP4 TP5 TP12: library part CMP-0055138-1, "Test Point, Miniature, Black, TH", Color=Black, Manufacturer=Keystone, PartNumber=5001, Supplier Part Number 1=36-5001-ND
TP6: library part CMP-0055141-1, "Test Point, Miniature, Yellow, TH", Color=Yellow, Manufacturer=Keystone, PartNumber=5004, Supplier Part Number 1=36-5004-ND
TP8 TP10: library part CMP-0003825-1, "1mm Test Point, SMT", Manufacturer=Any, PartNumber=TP_SM_1MM
TP9 TP11: library part CMP-0055139-1, "Test Point, Miniature, White, TH", Color=White, Manufacturer=Keystone, PartNumber=5002, Supplier Part Number 1=36-5002-ND
U1: library part CMP-0861102-1, "2.2MHz Wide VIN Boost/Sepic/Flyback Converter with Dual Random Spread Spectrum, RTE0016K (WQFN-16)", Alternate Manufacturer="Texas Instruments"
ZZ1: library part CMP-0003616-3
ZZ2: library part CMP-0077236-1
ZZ3: library part CMP-0077237-1
ZZ4: library part CMP-0077238-1
ZZ5 ZZ6: library part CMP-0077238-1, "These assemblies must comply with workmanship standards IPC-A-610 Class 2, unless otherwise specified."

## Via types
v1: diameter 22, hole 10, Top Layer to Bottom Layer, tented both sides, 119 vias
v2: diameter 19.68, hole 7.87, Top Layer to Bottom Layer, 5 vias

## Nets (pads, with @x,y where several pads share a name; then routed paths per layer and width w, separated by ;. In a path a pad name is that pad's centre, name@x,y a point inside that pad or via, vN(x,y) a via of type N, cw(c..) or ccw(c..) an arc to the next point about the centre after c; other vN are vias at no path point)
AGND: C24.2 C25.2 C27.2 D4.2 J10.3 NT1.2 Q1.2 R12.1 R13.1 R14.1 R15.2 R16.1 R17.1 R18.1 R19.1 R20.1 TP12.1 U1.7 | length 2950.7
  Top Layer w10: C24.2@1538.87,1558.44 R12.1@1538.87,1502.4 1543.09,1506.62 1566.43,1506.62 ; C25.2@1566.43,1290.09 R13.1@1566.43,1345.2 1566.43,1382.61 1581.44,1397.63 C27.2@1581.44,1398.61 1581.44,1474 R19.1@1582.44,1475 1571.69,1485.75 1571.69,1501.35 1566.43,1506.62 ; U1.7@1774.47,1386.54 1774.2,1386.82 1774.2,1403.8 1768.5,1409.5 ; 1778.24,1435 1778.24,1419.25 1768.5,1409.5 ; R14.1@1903,1489.81 1897.87,1494.94 1897.87,1515.56 1886.73,1526.7 1806.98,1526.7 1795,1514.72 1795,1429.89 1774.47,1409.5 1768.5,1409.5 ; 1566.43,1506.62 1605.8,1545.99 1668.79,1545.99 1720.11,1494.67 1720.11,1457.89 1768.5,1409.5
  Top Layer w12: R17.1@727,2240.44 800.07,2240.44 Q1.2@801.19,2239.32 798,2236.13 TP12.1@798,2137
  Top Layer w20: 795,1951.56 798,1954.56 TP12.1@798,2137 ; R20.1@1043,1956.37 R20.1@1047,1952.37
  Top Layer w24: R15.2@747,1951.56 795,1951.56 1046.19,1951.56 R20.1@1047,1952.37 ; 1605.8,1545.99 1606.98,1547.17 J10.3@1606.98,1980
  Signal Layer 1 w24: TP12.1@786,2139 796.09,2139.39 TP12.1@798.31,2137.33 ; TP12.1@798,2137 880,2055 1531.98,2055 J10.3@1606.98,1980
  Bottom Layer w20: v1(1565,1442.52) 1568.54,1446.05 D4.2@1595,1446.05
BIAS: J6.2 J7.2 J8.2 J9.2 R4.1 | length 934.4
  Top Layer w10: R4.1@2009.89,1421.56 2009.89,1454.89 2041,1486 v1(2041,1506.92)
  Signal Layer 2 w10: v1(2041,1506.92) 2041,1751 2096.67,1806.67 J7.2@2150,1806.67 J6.2@2290,1806.67 2333.07,1806.67 J9.2@2429.74,1710 J8.2@2570,1710
BIAS-IC: C22.1 J10.6 R4.2 U1.3 | length 742.4
  Top Layer w10: U1.3@1839.43,1341.27 1866.64,1341.27 1877.58,1352.2 1904.65,1352.2 C22.1@1917.44,1365 1917.44,1384.22 R4.2@1954.78,1421.56 1954.78,1449.78 v1@1960,1455
  Signal Layer 2 w10: J10.6@1906.98,1980 1906.98,1910 1954.78,1862.2 1954.78,1460.22 v1@1960,1455
  other v1: 1954.78,1455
